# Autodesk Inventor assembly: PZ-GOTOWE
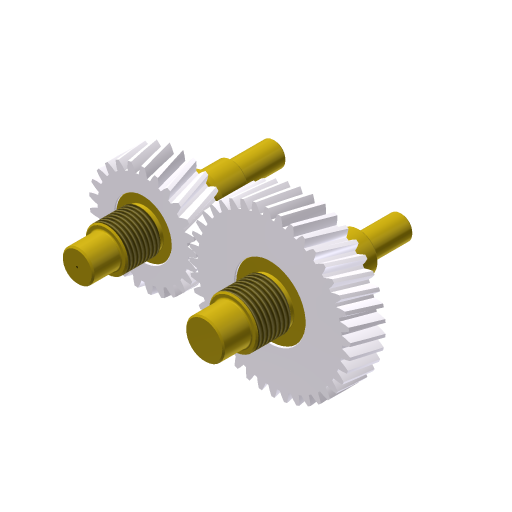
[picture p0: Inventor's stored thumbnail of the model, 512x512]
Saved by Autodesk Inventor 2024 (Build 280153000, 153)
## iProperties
Company: ATC
Created: 2023-03
Part Number: PZ-GOTOWE
Document SubType Name: Assembly
Designer: Andrzej Jaskulski
Checked By: A.J.
Engr Approved By: Andrzej Jaskulski
Mfg Approved By: Andrzej Jaskulski
Authority: A.J.
Title: A.J.: Kurs R2024-MEP
Author: Andrzej Jaskulski
Revision Number: 1/24
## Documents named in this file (4)
- C:\Users\AndJas\Documents\R2024-MEP\Obszar roboczy\PZ\GOTOWE\PZ-GOTOWE.iam
- C:\Users\AndJas\Documents\R2024-MEP\Obszar roboczy\PZ\GOTOWE\Wał1-gotowe.iam
- C:\Users\AndJas\Documents\R2024-MEP\Obszar roboczy\PZ\GOTOWE\Wał2-gotowe.iam
- C:\Users\AndJas\Documents\R2024-MEP\Obszar roboczy\PZ\GOTOWE\PZ-01-gotowe.iam
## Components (3 placed, 2 different names)
1. Wał:1 [sub-assembly] — Odległość osi, Zestawiający:15, Równoległy:7, Kąt:5, Zestawiający:17, Zestawiający:18
2. Wał:2 [sub-assembly] — Równoległy:5, Równoległy:6, Odległość osi, Równoległy:8, Kąt:6, Zestawiający:19
3. PZ-01:1 [sub-assembly] — Zestawiający:17, Zestawiający:18, Zestawiający:19
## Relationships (11: Mate 5, Flush 4, Angle 2)
- Równoległy:5 [Flush]: Wał:2
- Równoległy:6 [Flush]: Wał:2
- Odległość osi [Mate]: Wał:1 ↔ Wał:2
- Zestawiający:15 [Mate]: Wał:1
- Równoległy:7 [Flush]: Wał:1
- Kąt:5 [Angle]: Wał:1
- Równoległy:8 [Flush]: Wał:2
- Kąt:6 [Angle]: Wał:2
- Zestawiający:17 [Mate]: Wał:1 ↔ PZ-01:1
- Zestawiający:18 [Mate]: Wał:1 ↔ PZ-01:1
- Zestawiający:19 [Mate]: Wał:2 ↔ PZ-01:1
